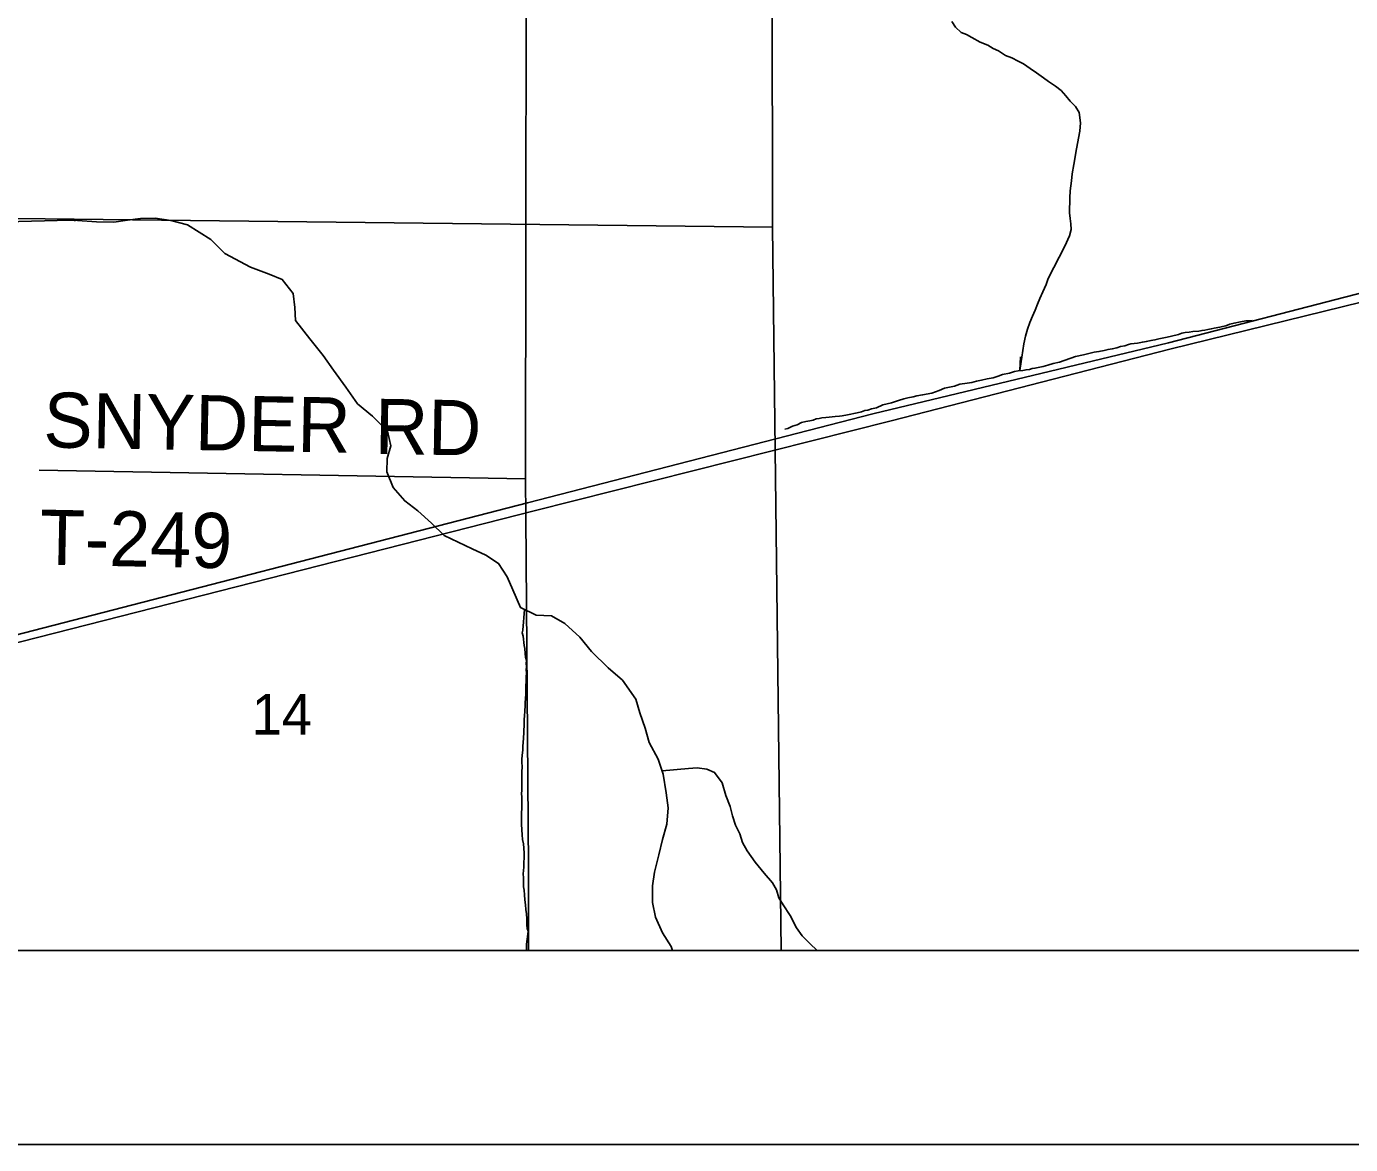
# Model space of a CAD drawing. Extents: x 0 to 34, y 0 to 22.
# Drawn here: x 5.357 to 6.04, y 14 to 14.576 of the extents above; entities that cross this region are included whole.
import ezdxf

# ---------------------------------------------------------------- set-up
doc = ezdxf.new("R2010")
doc.units = 0
for name, color, linetype in [('GM_X_Corporation', 7, 'Continuous'), ('GM_X_Minor_River', 7, 'Continuous'), ('GM_X_Rail_Line', 7, 'Continuous'), ('GM_X_Section_Text', 7, 'Continuous'), ('GM_X_Township_Road', 7, 'Continuous'), ('GM_X_Township_Road_Text', 7, 'Continuous'), ('SH_Data', 7, 'Continuous')]:
    doc.layers.add(name, color=color, linetype=linetype)

msp = doc.modelspace()

# ---------------------------------------------------------------- linework, layer by layer
at = {"layer": 'GM_X_Corporation'}
for points in [[(5.23798, 14.97858), (5.74097, 14.97364), (5.74155, 14.47285), (5.23138, 14.47865)], [(5.23631, 14.1), (5.74611, 14.1), (5.74155, 14.47285), (5.23138, 14.47865)]]:
    msp.add_lwpolyline(points, close=True, dxfattribs=at)
for points in [[(2.1, 14.1), (6.05687, 14.1)], [(3.23968, 14.1), (6.05687, 14.1)]]:
    msp.add_lwpolyline(points, dxfattribs=at)
at = {"layer": 'GM_X_Minor_River'}
for p, q in [((5.34657, 14.47571), (5.37934, 14.47652)), ((5.38162, 14.47631), (5.38225, 14.47632))]:
    msp.add_line(p, q, dxfattribs=at)
for points in [[(5.83406, 14.5789), (5.83589, 14.57601), (5.83888, 14.57328), (5.84171, 14.57227), (5.84434, 14.5707), (5.84866, 14.56832), (5.85261, 14.56671), (5.85543, 14.56494), (5.85806, 14.56375), (5.86182, 14.56138), (5.86502, 14.56017), (5.86822, 14.55839), (5.87104, 14.557), (5.87441, 14.55465), (5.87778, 14.55248), (5.88134, 14.54994), (5.88396, 14.54798), (5.88752, 14.54562), (5.89051, 14.54327), (5.89293, 14.54056), (5.89515, 14.53785), (5.89775, 14.53513)], [(5.89775, 14.53513), (5.89978, 14.53205), (5.90043, 14.52671), (5.90014, 14.52235), (5.89843, 14.51326), (5.89692, 14.50512), (5.89606, 14.50038), (5.89579, 14.49677), (5.89511, 14.49166), (5.89485, 14.48805), (5.89468, 14.48026), (5.895, 14.4774), (5.89551, 14.47454), (5.89564, 14.47168), (5.89481, 14.46847), (5.89241, 14.46301), (5.88369, 14.44647), (5.88268, 14.44326), (5.88107, 14.43949), (5.87948, 14.4361), (5.87828, 14.43328), (5.87707, 14.43007), (5.87568, 14.42706), (5.87427, 14.42367), (5.87306, 14.42027), (5.87203, 14.41668), (5.87119, 14.41271), (5.86921, 14.39895), (5.86953, 14.40609)], [(5.37917, 14.47647), (5.38325, 14.47627), (5.39312, 14.47568), (5.40205, 14.47548), (5.4091, 14.47647), (5.41577, 14.47728), (5.42338, 14.47749), (5.43134, 14.47637), (5.44004, 14.47409), (5.45204, 14.46661), (5.4593, 14.45923), (5.47246, 14.45229), (5.48207, 14.44866), (5.48886, 14.44586), (5.49441, 14.4387), (5.49539, 14.43146), (5.49563, 14.4248), (5.50303, 14.41532), (5.50989, 14.40681), (5.51523, 14.39909), (5.5217, 14.3904), (5.5276, 14.3819), (5.53545, 14.37546), (5.54308, 14.36769), (5.54482, 14.36024), (5.54297, 14.35363), (5.54282, 14.34679), (5.54607, 14.33873), (5.552, 14.33176), (5.55874, 14.32667), (5.56583, 14.32025), (5.57235, 14.31402), (5.57949, 14.31045), (5.58684, 14.30706), (5.5938, 14.30387), (5.60036, 14.29954), (5.60478, 14.2926), (5.60767, 14.28589), (5.61166, 14.27687), (5.61975, 14.27289), (5.62773, 14.27253), (5.63449, 14.26858), (5.64232, 14.26157), (5.64825, 14.25421), (5.65681, 14.24566), (5.66428, 14.23942), (5.6711, 14.22958), (5.67323, 14.2225), (5.67592, 14.21465), (5.67804, 14.20719), (5.68261, 14.19872), (5.68529, 14.19087), (5.6868, 14.18133), (5.68777, 14.17352), (5.68722, 14.16516), (5.68496, 14.15723), (5.68308, 14.14929), (5.6808, 14.1404), (5.67969, 14.13339), (5.6797, 14.12484), (5.68125, 14.1172), (5.68488, 14.10913), (5.68929, 14.10201), (5.69006, 14.1)], [(5.748, 14.36876), (5.74952, 14.36913), (5.75199, 14.37027), (5.75427, 14.37102), (5.75654, 14.37215), (5.75882, 14.37272), (5.76091, 14.37309), (5.76262, 14.37347), (5.76414, 14.37403), (5.76566, 14.37422), (5.76698, 14.37459), (5.76907, 14.37478), (5.77078, 14.37496), (5.7723, 14.37515), (5.774, 14.37534), (5.77609, 14.37552), (5.77761, 14.37571), (5.78027, 14.37608), (5.7852, 14.37721), (5.78748, 14.37777), (5.78919, 14.37833), (5.79071, 14.37852), (5.7926, 14.37927), (5.79526, 14.37984), (5.79849, 14.38135), (5.80305, 14.38229), (5.80665, 14.38361), (5.80931, 14.38436), (5.8114, 14.38492), (5.81406, 14.38549), (5.81595, 14.38586), (5.81899, 14.38642), (5.82374, 14.38736), (5.82753, 14.38868), (5.83038, 14.38981), (5.83551, 14.39094), (5.83816, 14.39188), (5.84196, 14.39244), (5.84443, 14.39281), (5.84671, 14.39357), (5.84936, 14.39394), (5.85221, 14.39469), (5.85544, 14.39525), (5.8579, 14.396), (5.86018, 14.39695), (5.86379, 14.3977), (5.86645, 14.39845), (5.86834, 14.39883), (5.87062, 14.39901), (5.87233, 14.39939), (5.87404, 14.39957), (5.87556, 14.39995), (5.87688, 14.40013), (5.87859, 14.40051), (5.88125, 14.40107), (5.88353, 14.40182), (5.88638, 14.40258), (5.8896, 14.40333), (5.89777, 14.40615), (5.90194, 14.40709), (5.90479, 14.40784), (5.90745, 14.40841), (5.90991, 14.40878), (5.91257, 14.40934), (5.91466, 14.40991), (5.91675, 14.41009), (5.91921, 14.41066), (5.92111, 14.41141), (5.9232, 14.41179), (5.9251, 14.41235), (5.92643, 14.41273), (5.92984, 14.4131), (5.93231, 14.41366), (5.9344, 14.41403), (5.93668, 14.41441), (5.93876, 14.41478), (5.94085, 14.41535), (5.94503, 14.4161), (5.9473, 14.41666), (5.95091, 14.4176), (5.95262, 14.41816), (5.95433, 14.41854), (5.95641, 14.41872), (5.95831, 14.4191), (5.96135, 14.41928), (5.96306, 14.41966), (5.96457, 14.41984), (5.96609, 14.42022), (5.9678, 14.4204), (5.96932, 14.42078), (5.97217, 14.42134), (5.97368, 14.42172), (5.97539, 14.42209), (5.97748, 14.42285), (5.97957, 14.42341), (5.98299, 14.42416), (5.98564, 14.42453), (5.98697, 14.42453), (5.98887, 14.42472)], [(5.61377, 14.27579), (5.61282, 14.26506), (5.61263, 14.26373), (5.613, 14.26202), (5.61319, 14.2605), (5.61337, 14.25879), (5.61356, 14.25727), (5.61393, 14.25575), (5.61412, 14.25309), (5.6143, 14.25119), (5.61486, 14.24948), (5.61467, 14.24796), (5.61485, 14.24644), (5.61466, 14.24473), (5.61484, 14.24322), (5.61465, 14.24113), (5.61464, 14.23866), (5.61444, 14.23657), (5.61443, 14.2322), (5.61404, 14.22765), (5.61403, 14.22632), (5.61384, 14.22347), (5.61383, 14.221), (5.61363, 14.2191), (5.61362, 14.21569), (5.61343, 14.21379), (5.61342, 14.21208), (5.61322, 14.2098), (5.61303, 14.20695), (5.61283, 14.20562), (5.61283, 14.20335), (5.61263, 14.20069), (5.61243, 14.19841), (5.61243, 14.19651), (5.61261, 14.19518), (5.61241, 14.19158), (5.61238, 14.18265), (5.61219, 14.18075), (5.61237, 14.17923), (5.61236, 14.17658), (5.61236, 14.17354), (5.61216, 14.17069), (5.61214, 14.16499), (5.6125, 14.15968), (5.61268, 14.15721), (5.61325, 14.15493), (5.61361, 14.15037), (5.61361, 14.14809), (5.61341, 14.14505), (5.6134, 14.14297), (5.61301, 14.13955), (5.61319, 14.13746), (5.61318, 14.1329), (5.61355, 14.13119), (5.61374, 14.12872), (5.61392, 14.12607), (5.61429, 14.1236), (5.61447, 14.12113), (5.61484, 14.11885), (5.61503, 14.11638), (5.61502, 14.11315), (5.6152, 14.11144), (5.61558, 14.10992), (5.61518, 14.10594), (5.6148, 14.10328), (5.61479, 14.1)], [(5.68468, 14.19265), (5.69828, 14.19382), (5.70285, 14.19411), (5.70778, 14.19343), (5.71174, 14.19182), (5.71561, 14.18642), (5.71757, 14.17991), (5.71972, 14.17416), (5.72095, 14.16938), (5.72256, 14.16459), (5.72475, 14.16017), (5.72617, 14.15577), (5.72855, 14.15135), (5.73261, 14.14556), (5.73724, 14.13994), (5.7417, 14.1349), (5.74371, 14.13125), (5.74495, 14.12723), (5.74716, 14.12357), (5.75065, 14.11798), (5.75394, 14.11164), (5.75689, 14.10758), (5.7608, 14.1037), (5.76469, 14.1)]]:
    msp.add_lwpolyline(points, dxfattribs=at)
at = {"layer": 'GM_X_Rail_Line'}
for points in [[(4.70996, 14.1), (4.85491, 14.13841), (5.34537, 14.26094), (5.61522, 14.33076), (5.79332, 14.37664), (5.94586, 14.41322), (6.04675, 14.43934), (6.04866, 14.43974)], [(4.72932, 14.1), (4.85491, 14.13304), (5.34586, 14.25704), (5.61879, 14.32659), (5.80285, 14.37307), (5.94645, 14.40994), (6.04585, 14.43443), (6.0488, 14.43506)]]:
    msp.add_lwpolyline(points, dxfattribs=at)
at = {"layer": 'GM_X_Township_Road'}
msp.add_line((5.3635, 14.34768), (5.61428, 14.34317), dxfattribs=at)
for points in [[(5.61443, 14.32365), (5.61428, 14.34317), (5.61476, 14.71793), (5.62144, 15.34871)], [(5.61576, 14.1), (5.61578, 14.14304), (5.61443, 14.32365)]]:
    msp.add_lwpolyline(points, dxfattribs=at)
at = {"layer": 'SH_Data'}
for p, q in [((2.1, 14.1), (8.9, 14.1)), ((2.1, 14.1), (8.9, 14.1)), ((2, 14), (9, 14)), ((2, 14), (9, 14))]:
    msp.add_line(p, q, dxfattribs=at)

# ---------------------------------------------------------------- texts
at = {"layer": 'GM_X_Section_Text'}
msp.add_text('14', height=0.020928, rotation=0.00001, dxfattribs=at).set_placement((5.47308, 14.21133))
at = {"layer": 'GM_X_Township_Road_Text'}
for s, rotation, p in [('SNYDER', 358.96767, (5.36558, 14.35941)), ('RD', 359.01276, (5.5364, 14.35607)), ('T-249', 358.87626, (5.36357, 14.29893))]:
    msp.add_text(s, height=0.028409, rotation=rotation, dxfattribs=at).set_placement(p)

doc.saveas('drawing.dxf')
